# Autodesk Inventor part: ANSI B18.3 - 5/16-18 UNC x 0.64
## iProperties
Created: 2005-06
Part Number: ANSI B18.3 - 5/16-18 UNC x 0.64
Vendor: Autodesk Inc.
Document SubType Name: Modeling
Designer: John Blackburn
Material: Default
Description: Hexagon Socket Set Screw - Half Dog Point
Standard: ANSI B18.3
Size Designation: 5/16-18 UNC x 0.64
Control State: 0
Master: False
Checked Out: False
Shininess: 64.0
Length Units: 11272
Angle Units: 11279
Time Units: 11290
Mass Units: 11286
Length Display Precision: 3
Angle Display Precision: 2
Compacted: True
EGR: 3
Classification: un/spsc 31161505
Density: 0.0
Volumn: 0.0
Area: 0.0
PropertySet Name: Model Information
Author: John Blackburn
Revision Number: 8
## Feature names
1. Body [Revolution]
2. Chamfer1
3. Slot [Extrusion]
4. Chamfer2
